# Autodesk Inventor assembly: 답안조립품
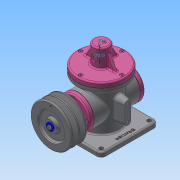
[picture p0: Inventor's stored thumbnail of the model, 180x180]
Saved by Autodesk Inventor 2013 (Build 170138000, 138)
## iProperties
Created: 2020-02
Part Number: 답안조립품
Document SubType Name: Assembly
Designer: Administrator
Mass: 2563.94 g
Surface Area: 2487.92 cm^2
Volume: 789.934 cm^3
Density: 3.24576 g/cm^3
Author: Administrator
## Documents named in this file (21)
- C:\Users\Administrator\Desktop\600206V1005\답안조립품.iam
- C:\Users\Administrator\Desktop\600206V1005\본체.ipt
- C:\Users\Administrator\Desktop\600206V1005\E-링.ipt
- C:\Users\Administrator\Desktop\600206V1005\V-벨트풀리.ipt
- C:\Users\Administrator\Desktop\600206V1005\가변스프링.ipt
- C:\Users\Administrator\Desktop\600206V1005\개스킷 A.ipt
- C:\Users\Administrator\Desktop\600206V1005\개스킷 B.ipt
- C:\Users\Administrator\Desktop\600206V1005\덮개.ipt
- C:\Users\Administrator\Desktop\600206V1005\뒤커버.ipt
- C:\Users\Administrator\Desktop\600206V1005\링크.ipt
- C:\Users\Administrator\Desktop\600206V1005\베어링 17 x 40 x 12.ipt
- C:\Users\Administrator\Desktop\600206V1005\볼트 M4 x 10.ipt
- C:\Users\Administrator\Desktop\600206V1005\슬라이더.ipt
- C:\Users\Administrator\Desktop\600206V1005\앞커버.ipt
- C:\Users\Administrator\Desktop\600206V1005\오일 실 17 30 8.ipt
- C:\Users\Administrator\Desktop\600206V1005\와셔 4x16.ipt
- C:\Users\Administrator\Desktop\600206V1005\육각 소켓 머리 볼트 M4 x 10.ipt
- C:\Users\Administrator\Desktop\600206V1005\클레비스 핀 6 x 22.ipt
- 클레비스 핀 6 x 22.ipt
- C:\Users\Administrator\Desktop\600206V1005\키 4 x 4 x 25.ipt
- C:\Users\Administrator\Desktop\600206V1005\편심축.ipt
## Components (6 placed, 5 different names)
1. 개스킷 B:1
2. 가변스프링:1
3. 개스킷 A:1
4. 개스킷 A:2
5. E-링:1
6. V-벨트풀리:1 — 플러쉬:1
## Component patterns: 구성요소 패턴 1:1 (4 elements), 구성요소 패턴 2:1 (4 elements), 구성요소 패턴 3:1 (4 elements)
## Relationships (1: Flush 1)
- 플러쉬:1 [Flush]: V-벨트풀리:1
